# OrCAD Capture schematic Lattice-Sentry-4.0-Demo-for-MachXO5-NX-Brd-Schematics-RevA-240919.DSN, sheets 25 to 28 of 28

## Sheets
25 LEDS: size B
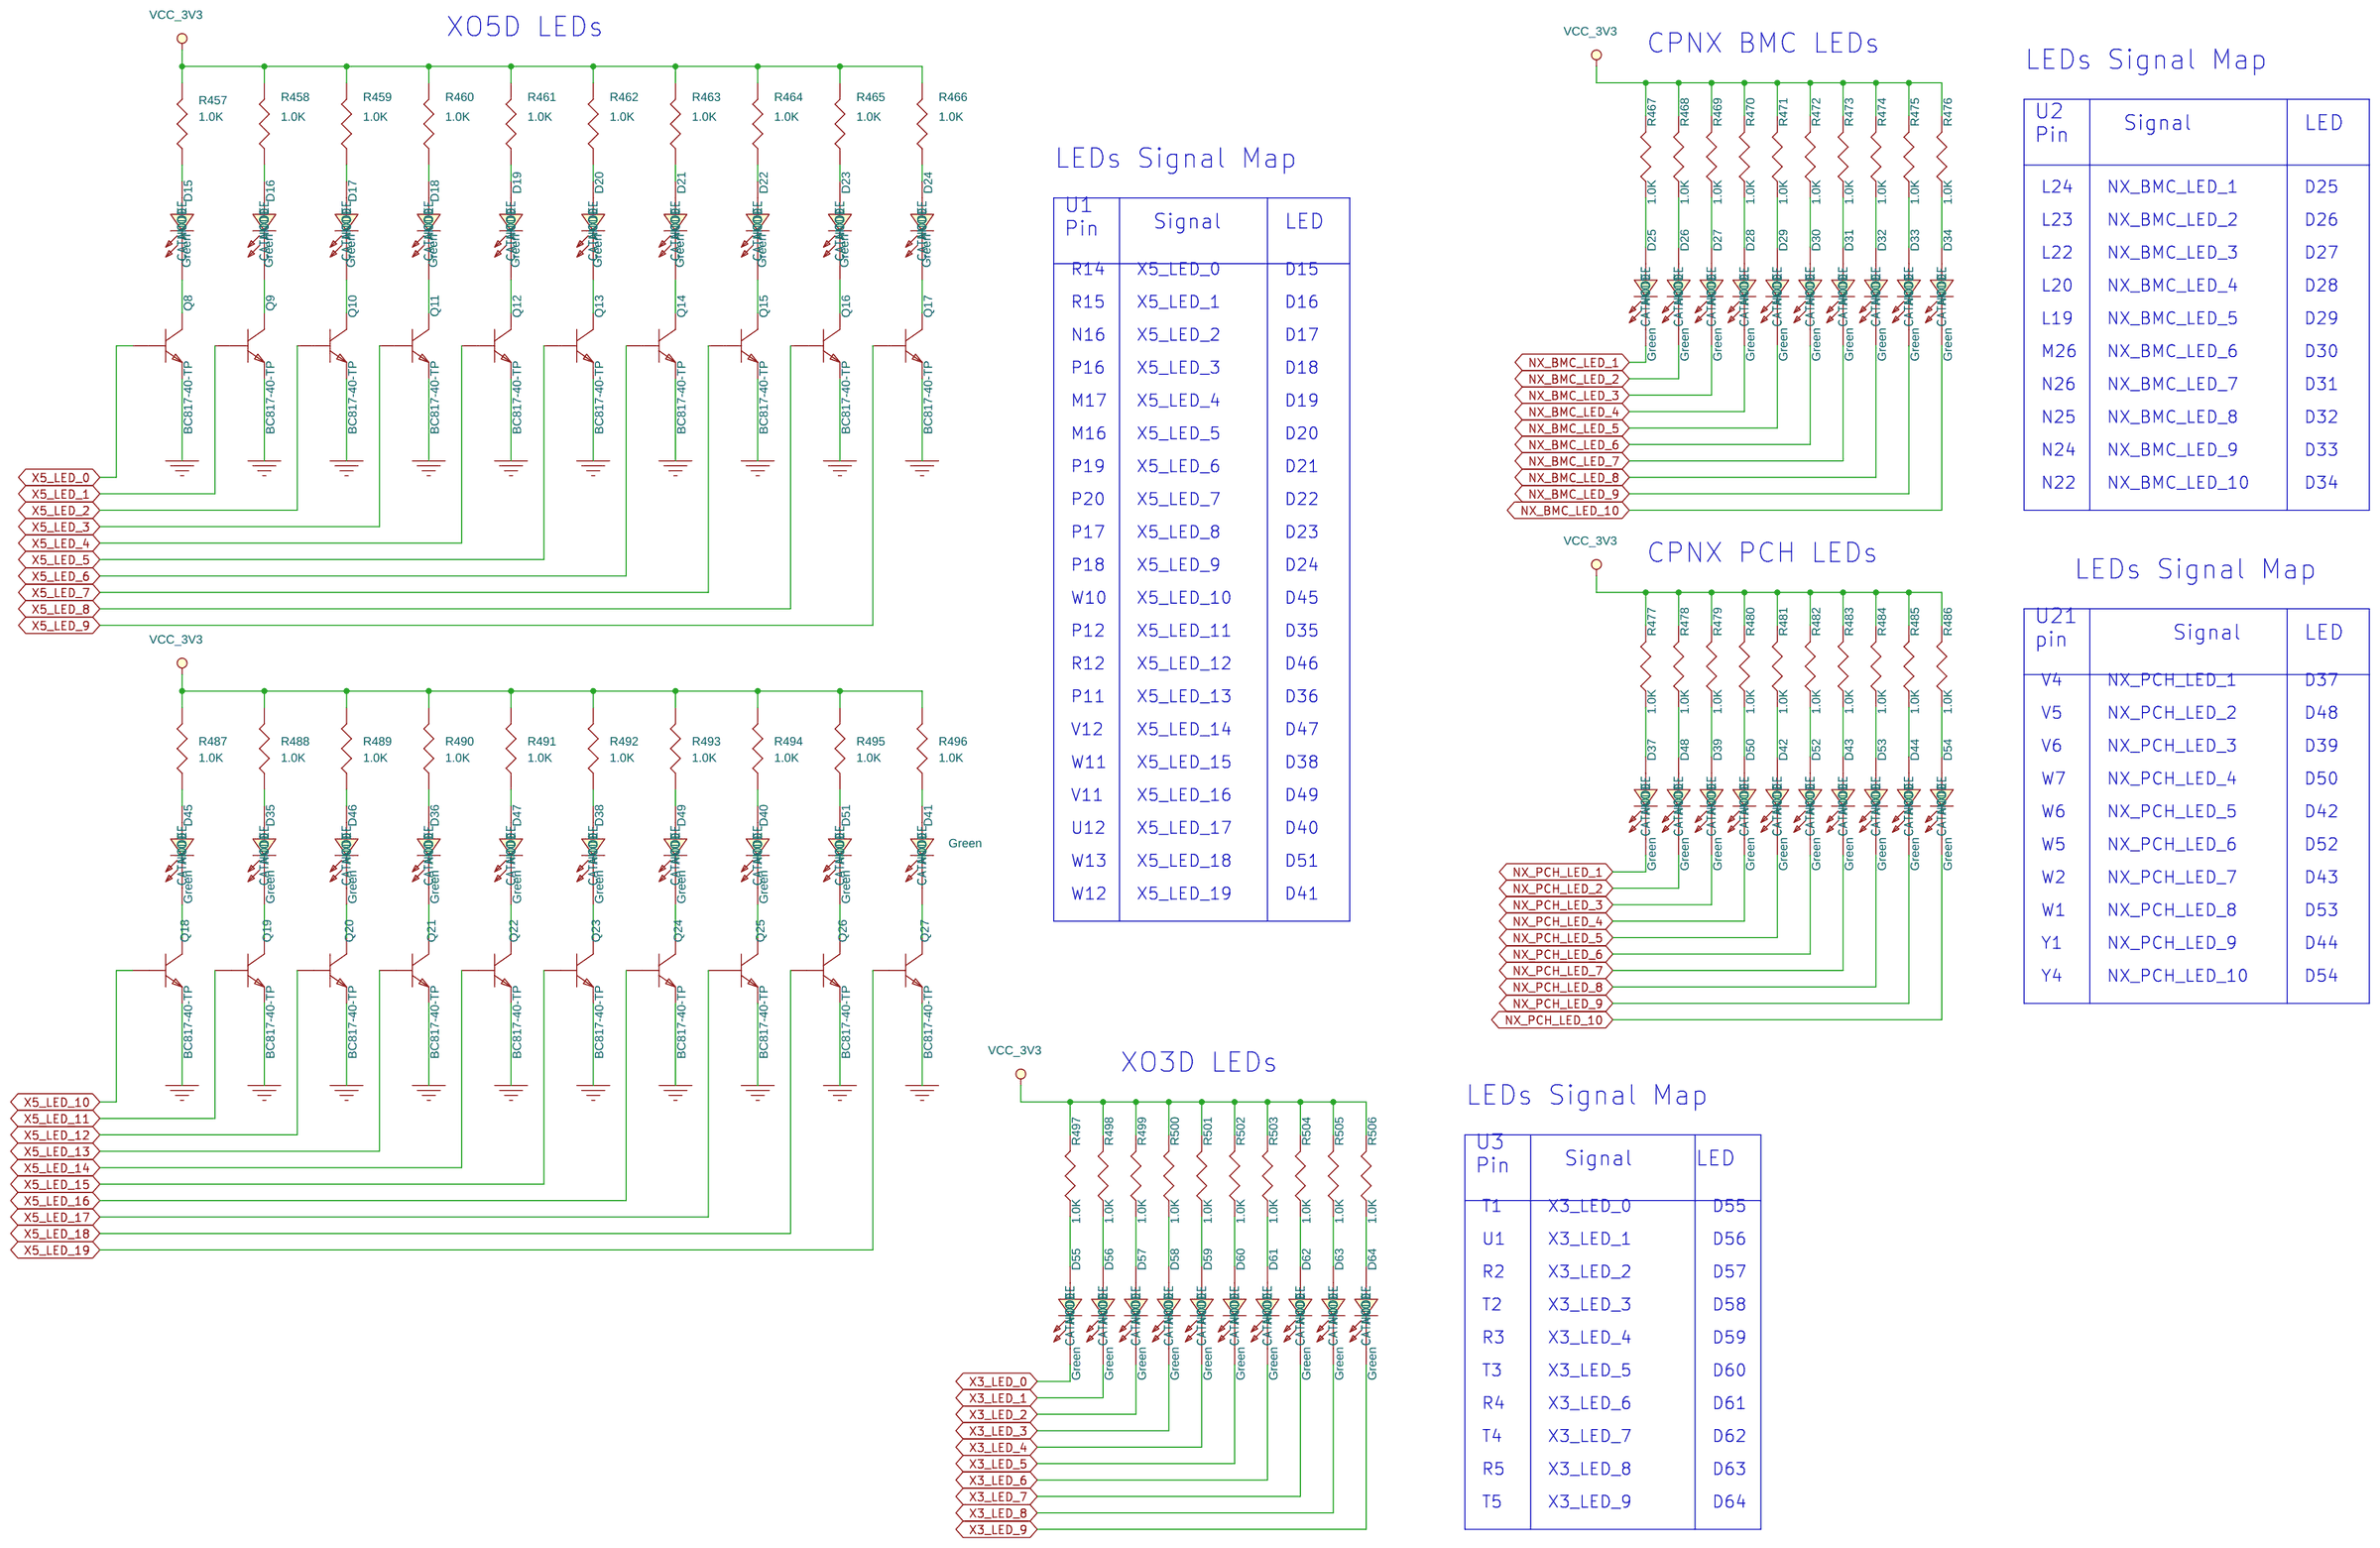
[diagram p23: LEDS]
26 DC-SCM CONNECTORS: size B
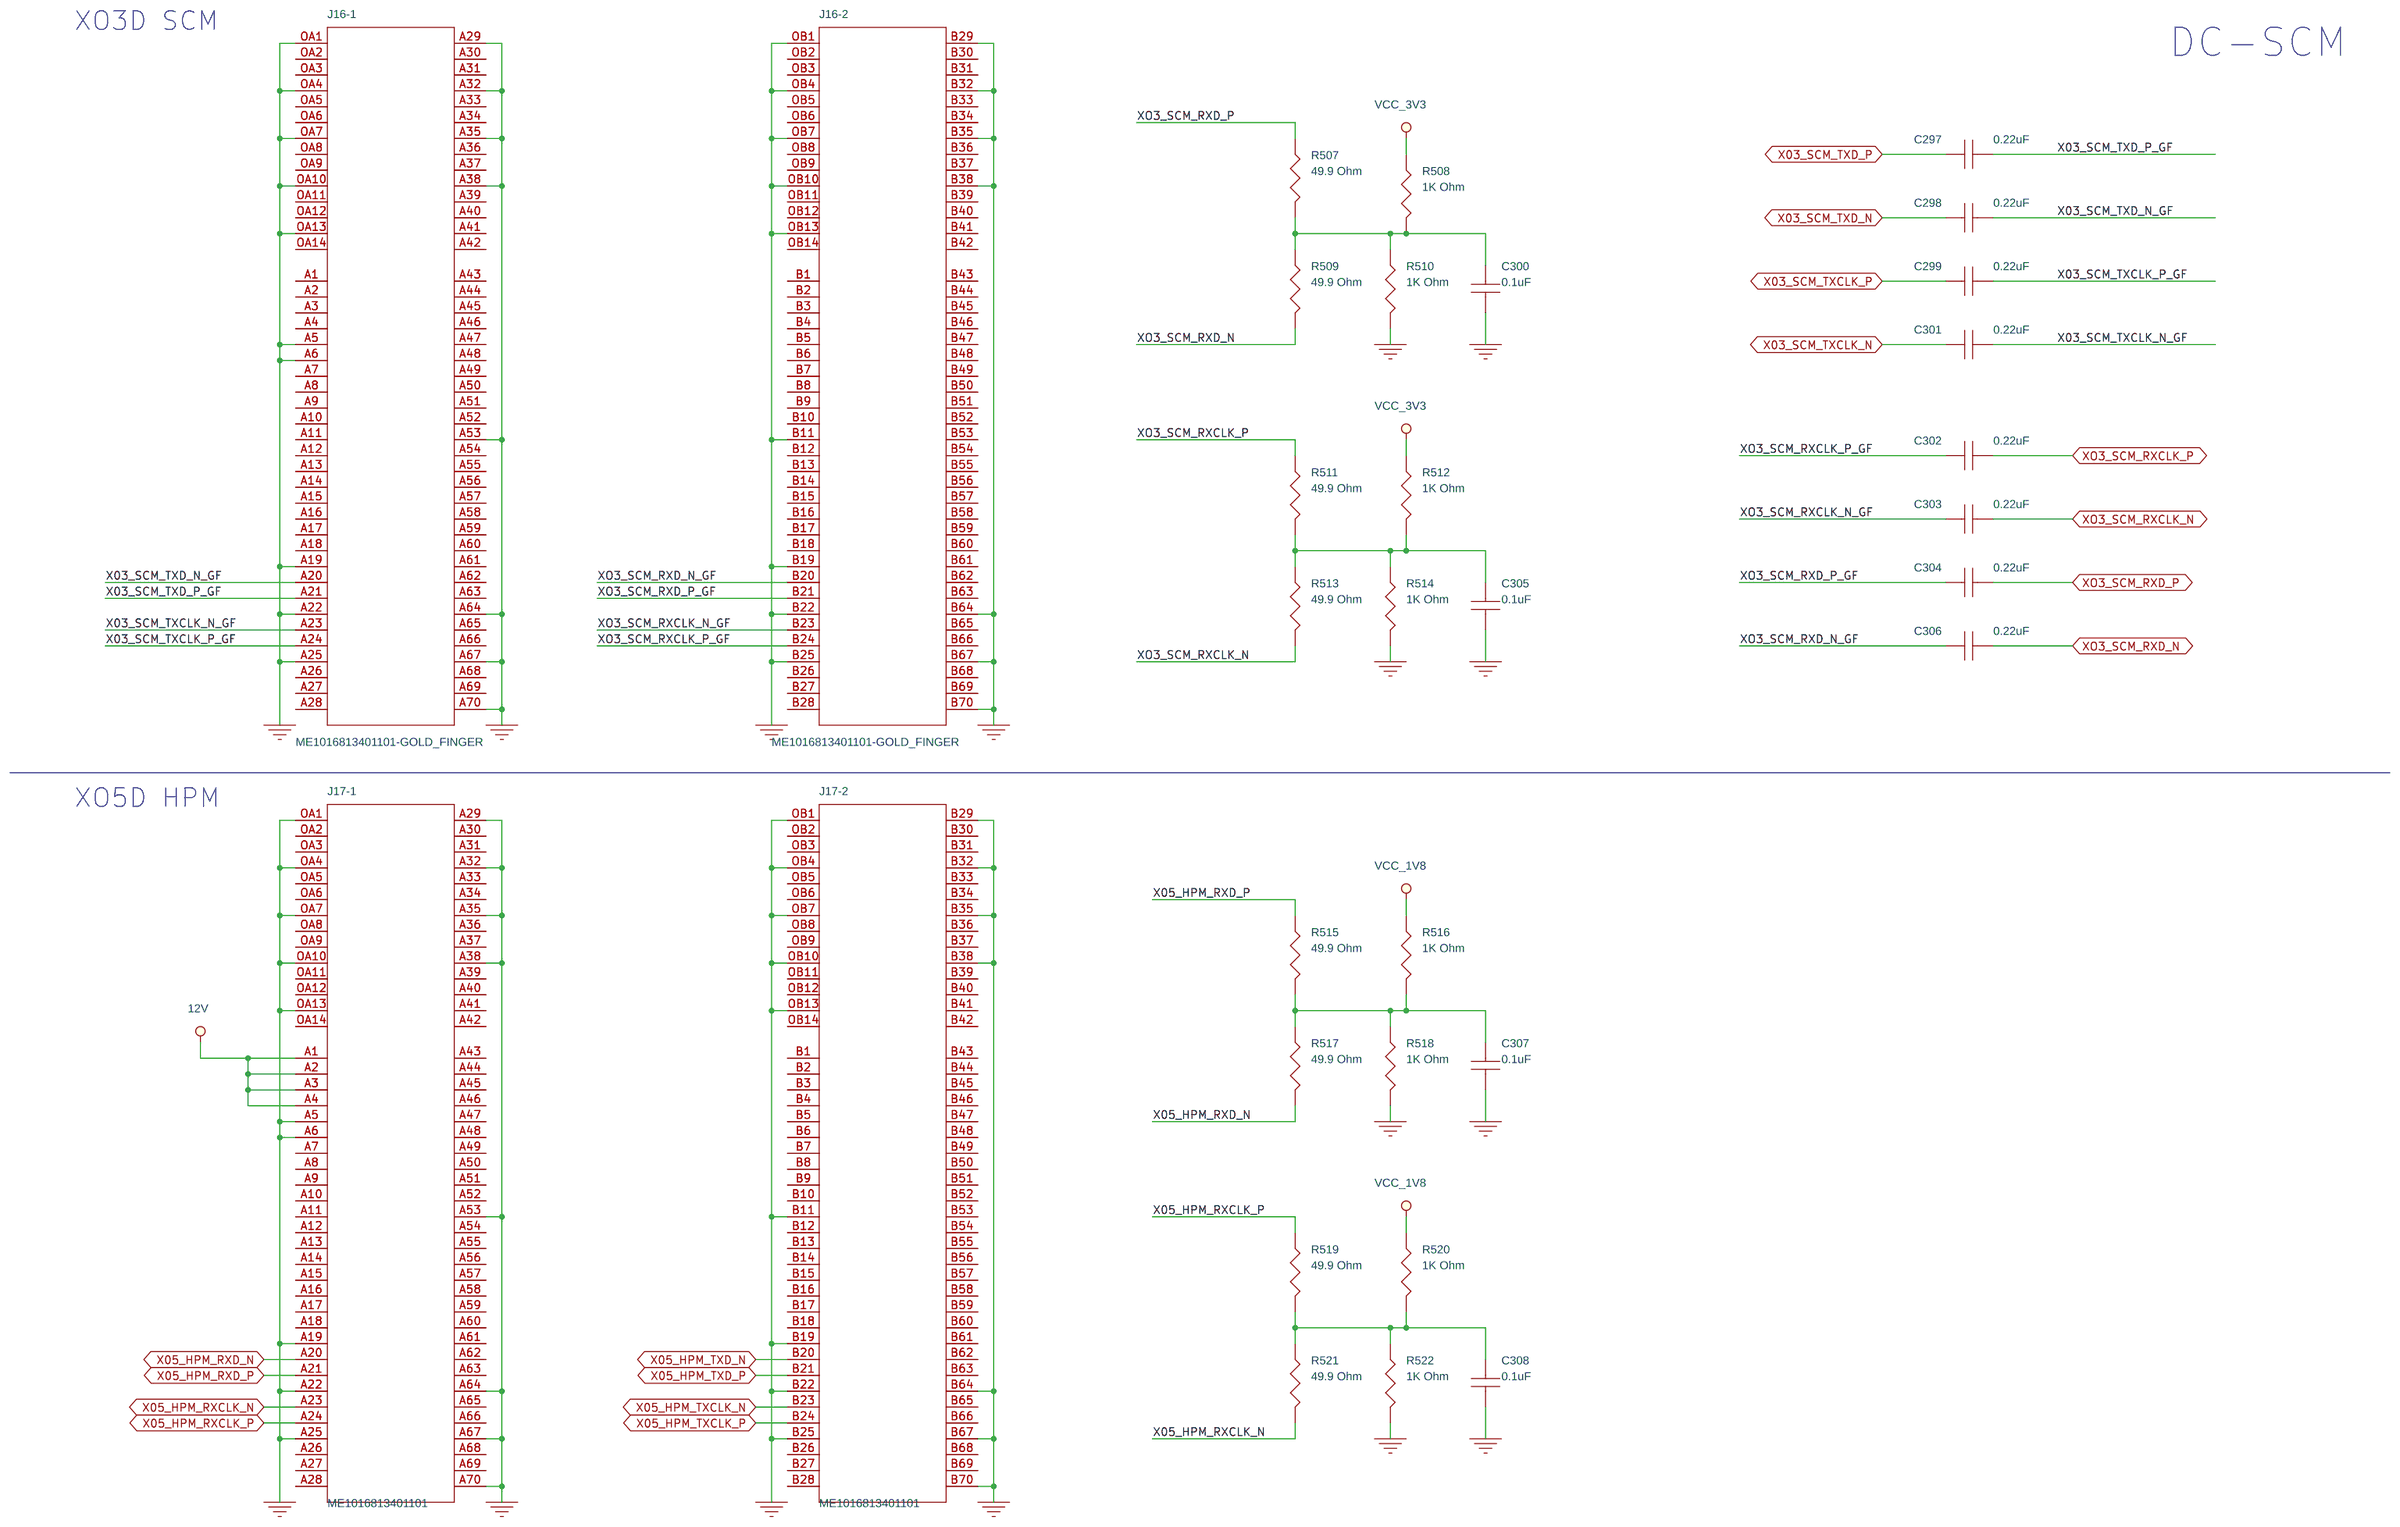
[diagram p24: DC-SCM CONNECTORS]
27 I3C PU: size B
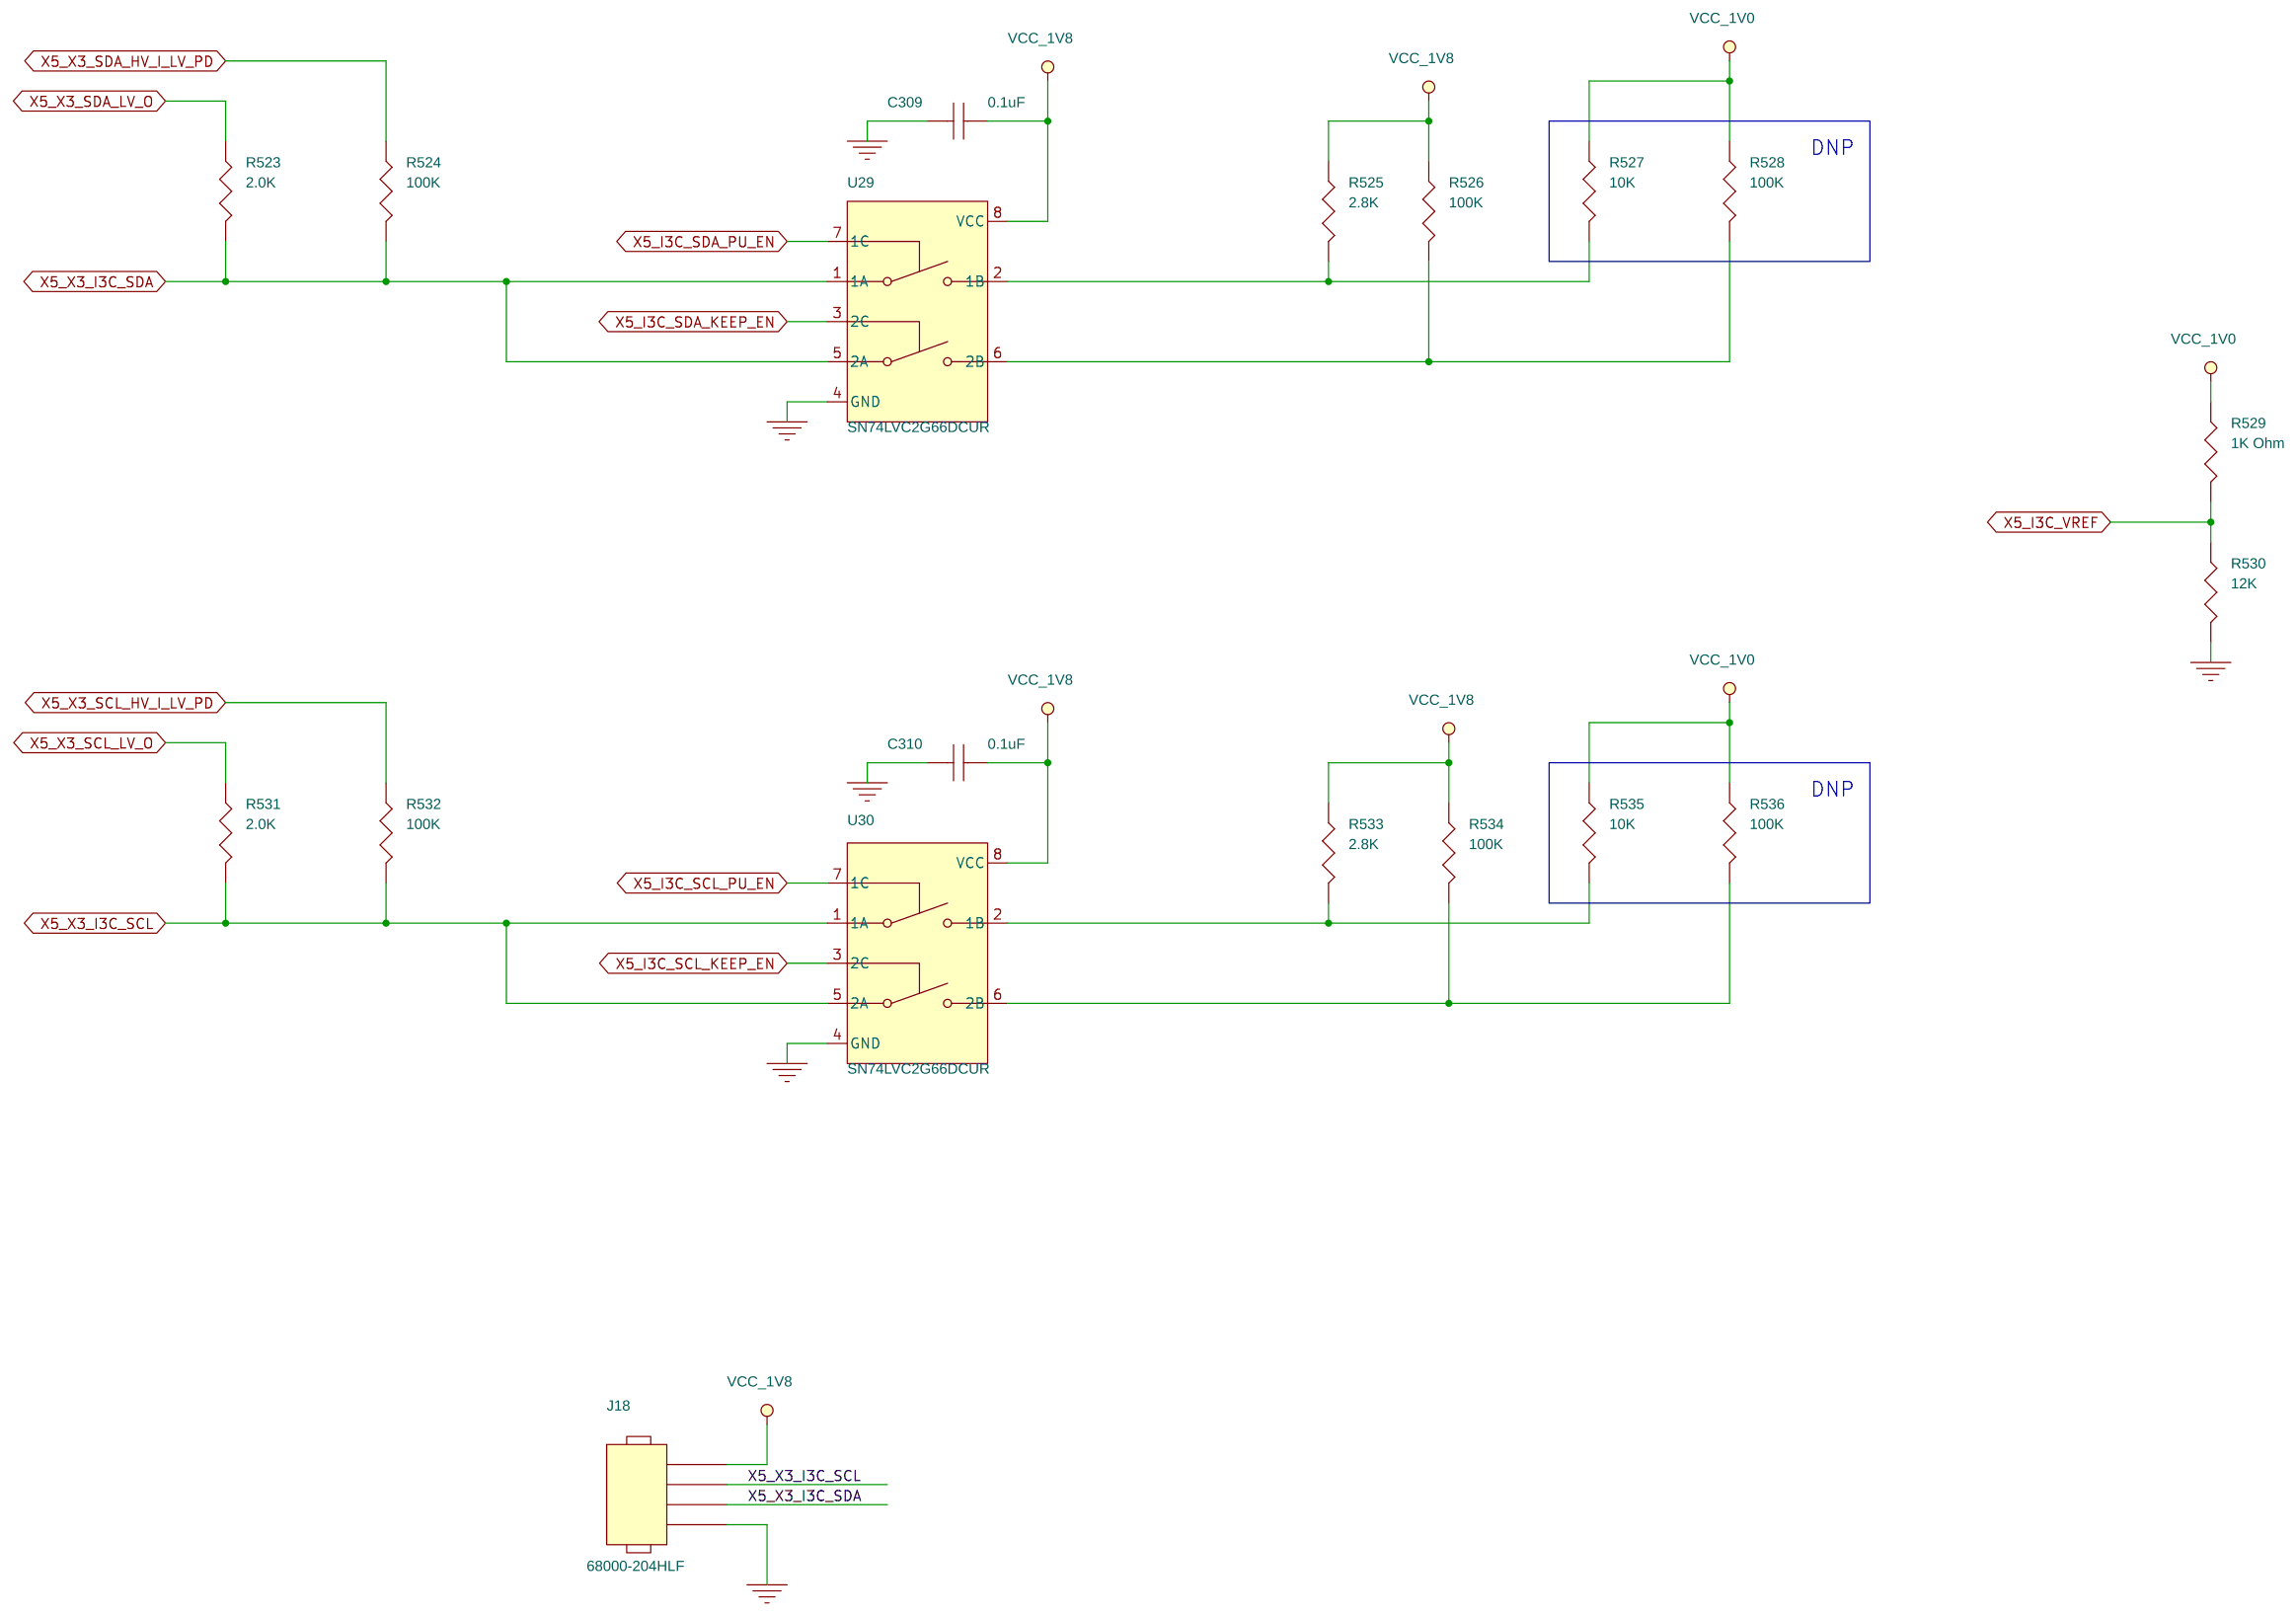
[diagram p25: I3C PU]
28 Power Regulators: size B
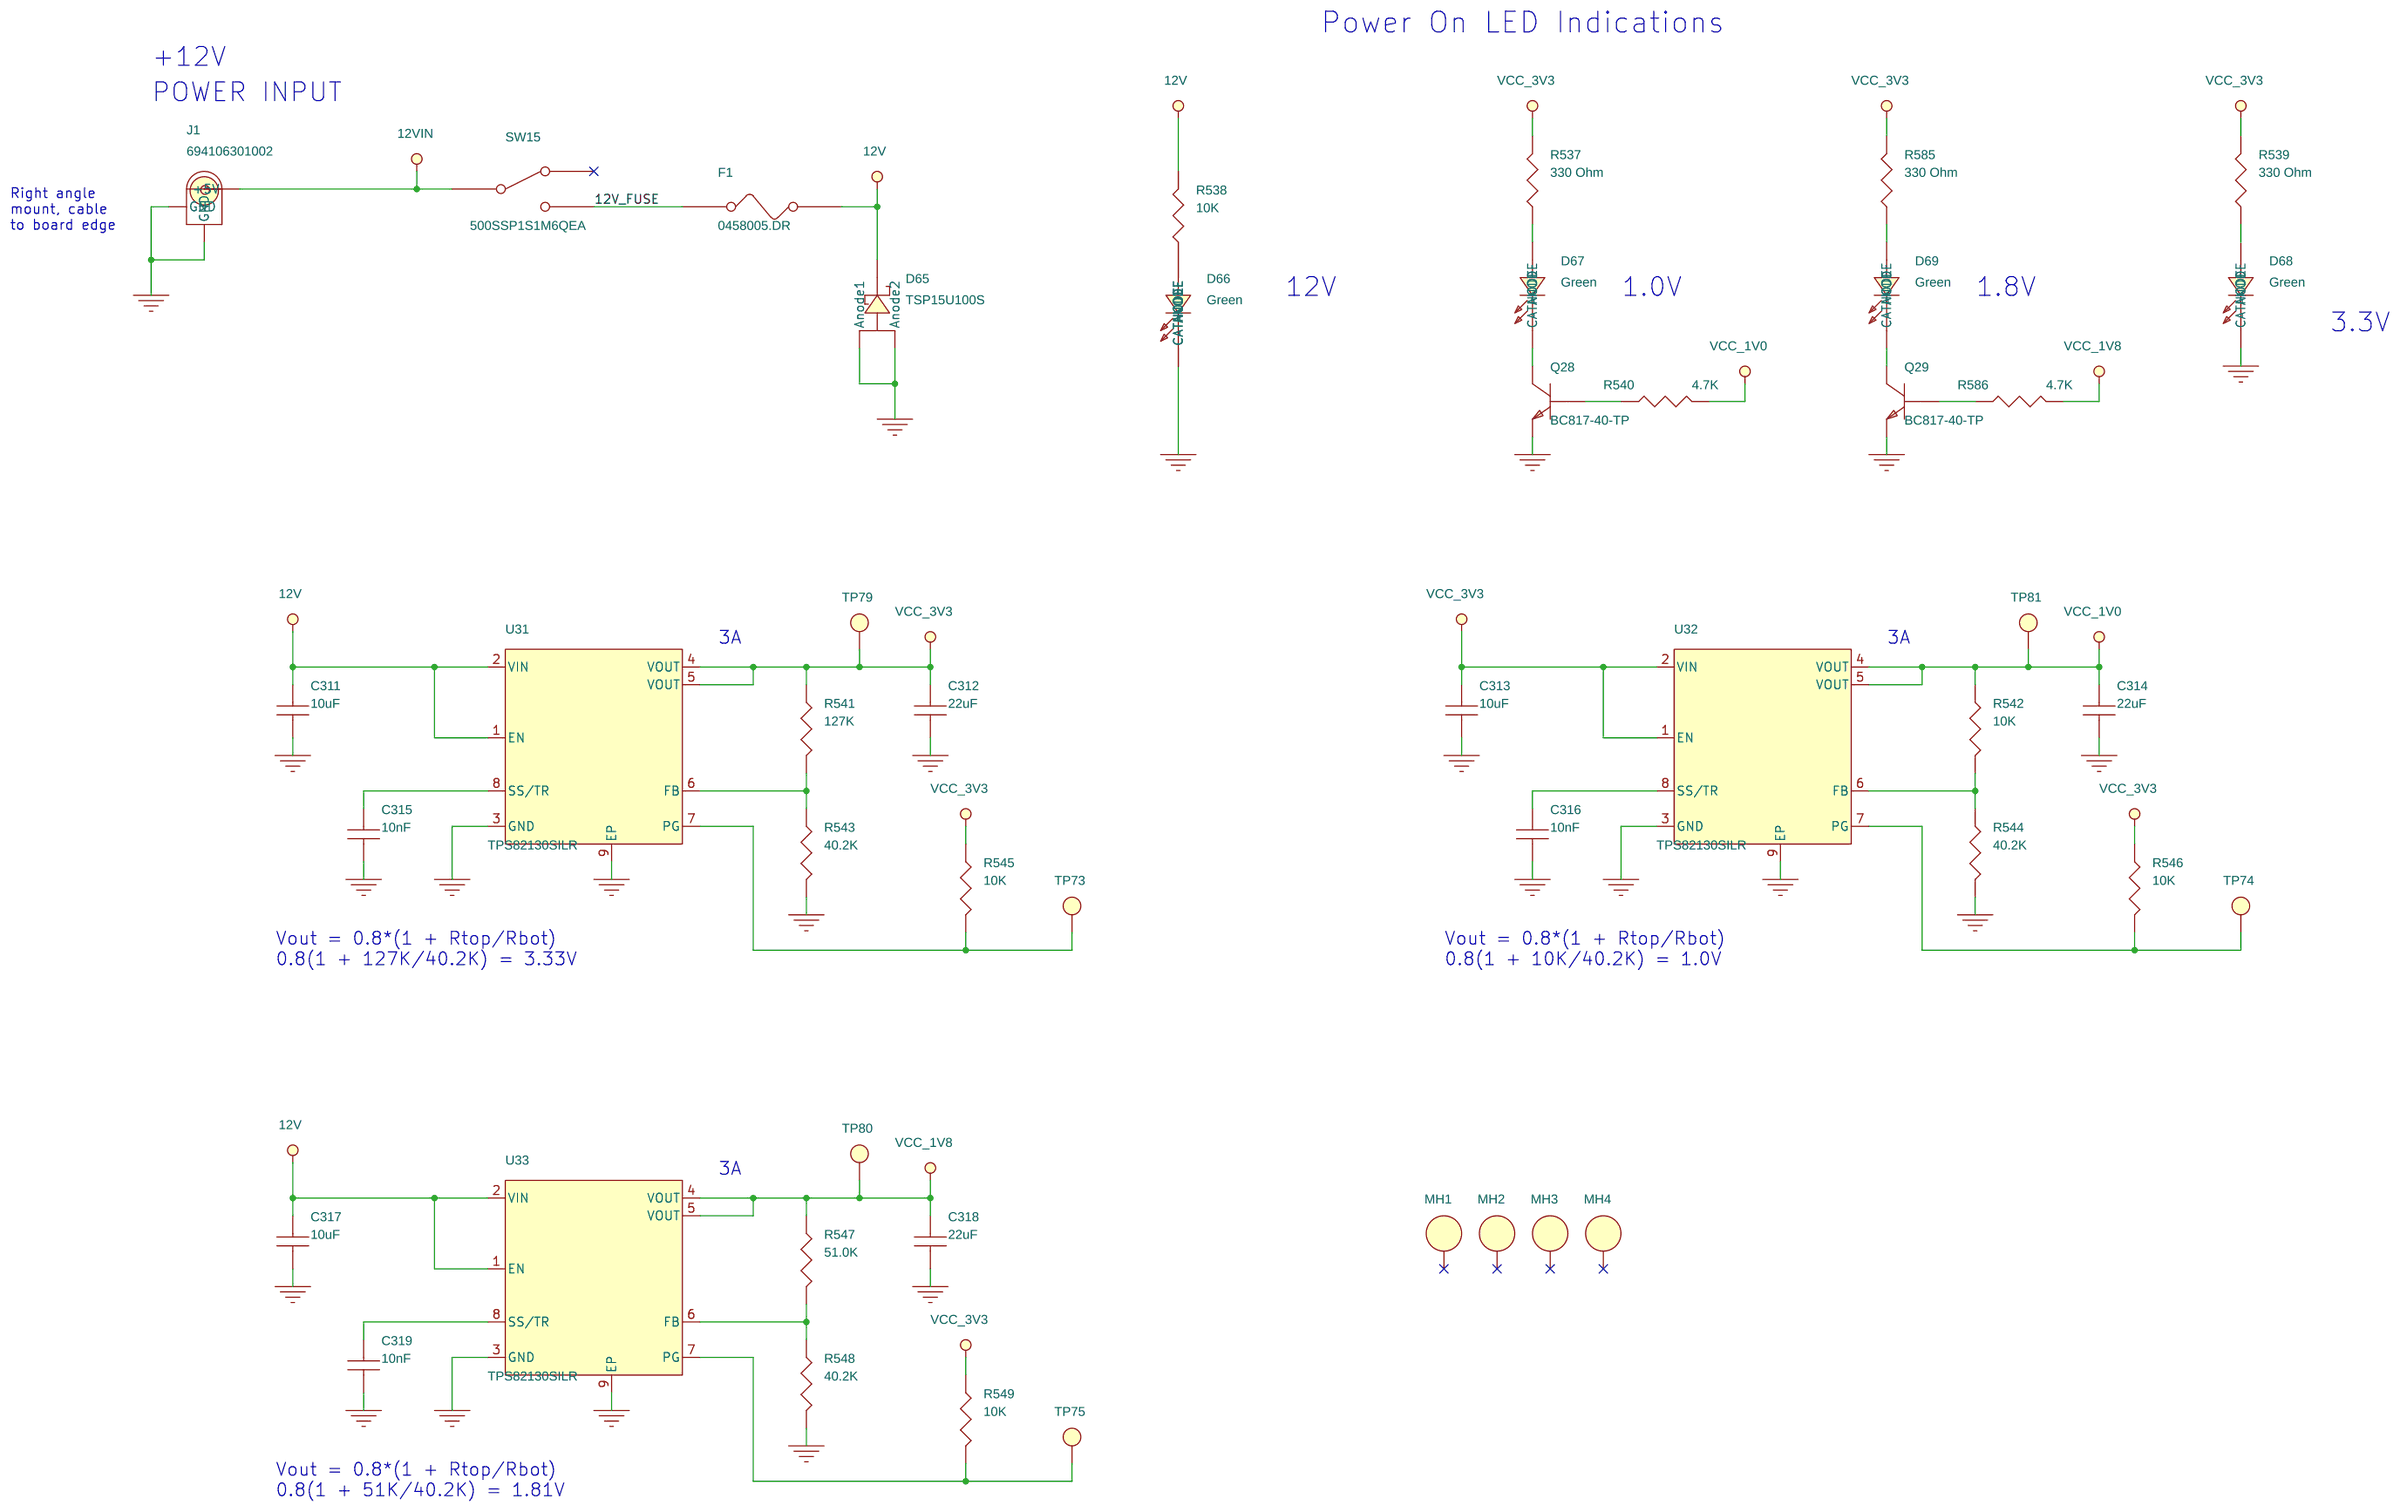
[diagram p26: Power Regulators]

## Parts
sheet DC-SCM CONNECTORS
C297  0.22uF  [C0402-L]
C298  0.22uF  [C0402-L]
C299  0.22uF  [C0402-L]
C300  0.1uF  [C0402-L]
C301  0.22uF  [C0402-L]
C302  0.22uF  [C0402-L]
C303  0.22uF  [C0402-L]
C304  0.22uF  [C0402-L]
C305  0.1uF  [C0402-L]
C306  0.22uF  [C0402-L]
C307  0.1uF  [C0402-L]
C308  0.1uF  [C0402-L]
J16  ME1016813401101-GOLD_FINGER  [AMPHENOL_ME1016813401101_GF]  (sections -1,-2)
J17  ME1016813401101  [AMPHENOL_ME1016813401101]  (sections -1,-2)
R507  49.9 Ohm  [R0402-L]
R508  1K Ohm  [R0402-L]
R509  49.9 Ohm  [R0402-L]
R510  1K Ohm  [R0402-L]
R511  49.9 Ohm  [R0402-L]
R512  1K Ohm  [R0402-L]
R513  49.9 Ohm  [R0402-L]
R514  1K Ohm  [R0402-L]
R515  49.9 Ohm  [R0402-L]
R516  1K Ohm  [R0402-L]
R517  49.9 Ohm  [R0402-L]
R518  1K Ohm  [R0402-L]
R519  49.9 Ohm  [R0402-L]
R520  1K Ohm  [R0402-L]
R521  49.9 Ohm  [R0402-L]
R522  1K Ohm  [R0402-L]
sheet I3C PU
C309  0.1uF  [C0402-L]
C310  0.1uF  [C0402-L]
J18  68000-204HLF  [CONN_61300411121_WRE]
R523  2.0K  [R0402-L]
R524  100K  [R0402-L]
R525  2.8K  [R0402-L]
R526  100K  [R0402-L]
R527  10K  [R0402-L]
R528  100K  [R0402-L]
R529  1K Ohm  [R0402-L]
R530  12K  [R0402-L]
R531  2.0K  [R0402-L]
R532  100K  [R0402-L]
R533  2.8K  [R0402-L]
R534  100K  [R0402-L]
R535  10K  [R0402-L]
R536  100K  [R0402-L]
U29  SN74LVC2G66DCUR  [DCU8]
U30  SN74LVC2G66DCUR  [DCU8]
sheet LEDS
D15  Green  [LED0603]
D16  Green  [LED0603]
D17  Green  [LED0603]
D18  Green  [LED0603]
D19  Green  [LED0603]
D20  Green  [LED0603]
D21  Green  [LED0603]
D22  Green  [LED0603]
D23  Green  [LED0603]
D24  Green  [LED0603]
D25  Green  [LED0603]
D26  Green  [LED0603]
D27  Green  [LED0603]
D28  Green  [LED0603]
D29  Green  [LED0603]
D30  Green  [LED0603]
D31  Green  [LED0603]
D32  Green  [LED0603]
D33  Green  [LED0603]
D34  Green  [LED0603]
D35  Green  [LED0603]
D36  Green  [LED0603]
D37  Green  [LED0603]
D38  Green  [LED0603]
D39  Green  [LED0603]
D40  Green  [LED0603]
D41  Green  [LED0603]
D42  Green  [LED0603]
D43  Green  [LED0603]
D44  Green  [LED0603]
D45  Green  [LED0603]
D46  Green  [LED0603]
D47  Green  [LED0603]
D48  Green  [LED0603]
D49  Green  [LED0603]
D50  Green  [LED0603]
D51  Green  [LED0603]
D52  Green  [LED0603]
D53  Green  [LED0603]
D54  Green  [LED0603]
D55  Green  [LED0603]
D56  Green  [LED0603]
D57  Green  [LED0603]
D58  Green  [LED0603]
D59  Green  [LED0603]
D60  Green  [LED0603]
D61  Green  [LED0603]
D62  Green  [LED0603]
D63  Green  [LED0603]
D64  Green  [LED0603]
Q8  BC817-40-TP  [SOT-23-3]
Q9  BC817-40-TP  [SOT-23-3]
Q10  BC817-40-TP  [SOT-23-3]
Q11  BC817-40-TP  [SOT-23-3]
Q12  BC817-40-TP  [SOT-23-3]
Q13  BC817-40-TP  [SOT-23-3]
Q14  BC817-40-TP  [SOT-23-3]
Q15  BC817-40-TP  [SOT-23-3]
Q16  BC817-40-TP  [SOT-23-3]
Q17  BC817-40-TP  [SOT-23-3]
Q18  BC817-40-TP  [SOT-23-3]
Q19  BC817-40-TP  [SOT-23-3]
Q20  BC817-40-TP  [SOT-23-3]
Q21  BC817-40-TP  [SOT-23-3]
Q22  BC817-40-TP  [SOT-23-3]
Q23  BC817-40-TP  [SOT-23-3]
Q24  BC817-40-TP  [SOT-23-3]
Q25  BC817-40-TP  [SOT-23-3]
Q26  BC817-40-TP  [SOT-23-3]
Q27  BC817-40-TP  [SOT-23-3]
R457  1.0K  [R0603-L]
R458  1.0K  [R0603-L]
R459  1.0K  [R0603-L]
R460  1.0K  [R0603-L]
R461  1.0K  [R0603-L]
R462  1.0K  [R0603-L]
R463  1.0K  [R0603-L]
R464  1.0K  [R0603-L]
R465  1.0K  [R0603-L]
R466  1.0K  [R0603-L]
R467  1.0K  [R0603-L]
R468  1.0K  [R0603-L]
R469  1.0K  [R0603-L]
R470  1.0K  [R0603-L]
R471  1.0K  [R0603-L]
R472  1.0K  [R0603-L]
R473  1.0K  [R0603-L]
R474  1.0K  [R0603-L]
R475  1.0K  [R0603-L]
R476  1.0K  [R0603-L]
R477  1.0K  [R0603-L]
R478  1.0K  [R0603-L]
R479  1.0K  [R0603-L]
R480  1.0K  [R0603-L]
R481  1.0K  [R0603-L]
R482  1.0K  [R0603-L]
R483  1.0K  [R0603-L]
R484  1.0K  [R0603-L]
R485  1.0K  [R0603-L]
R486  1.0K  [R0603-L]
R487  1.0K  [R0603-L]
R488  1.0K  [R0603-L]
R489  1.0K  [R0603-L]
R490  1.0K  [R0603-L]
R491  1.0K  [R0603-L]
R492  1.0K  [R0603-L]
R493  1.0K  [R0603-L]
R494  1.0K  [R0603-L]
R495  1.0K  [R0603-L]
R496  1.0K  [R0603-L]
R497  1.0K  [R0603-L]
R498  1.0K  [R0603-L]
R499  1.0K  [R0603-L]
R500  1.0K  [R0603-L]
R501  1.0K  [R0603-L]
R502  1.0K  [R0603-L]
R503  1.0K  [R0603-L]
R504  1.0K  [R0603-L]
R505  1.0K  [R0603-L]
R506  1.0K  [R0603-L]
sheet Power Regulators
C311  10uF  [C0805-L]
C312  22uF  [C0805-L]
C313  10uF  [C0805-L]
C314  22uF  [C0805-L]
C315  10nF  [C0402-L]
C316  10nF  [C0402-L]
C317  10uF  [C0805-L]
C318  22uF  [C0805-L]
C319  10nF  [C0402-L]
D65  TSP15U100S  [TO-227A_TS]
D66  Green  [LED0603]
D67  Green  [LED0603]
D68  Green  [LED0603]
D69  Green  [LED0603]
F1  0458005.DR  [0458Series_LTF-L]
J1  694106301002  [CONN3_01002_WRE]
MH1  MH  [MTG125]
MH2  MH  [MTG125]
MH3  MH  [MTG125]
MH4  MH  [MTG125]
Q28  BC817-40-TP  [SOT-23-3]
Q29  BC817-40-TP  [SOT-23-3]
R537  330 Ohm  [R0402-L]
R538  10K  [R0402-L]
R539  330 Ohm  [R0402-L]
R540  4.7K  [R0402-L]
R541  127K  [R0402-L]
R542  10K  [R0402-L]
R543  40.2K  [R0402-L]
R544  40.2K  [R0402-L]
R545  10K  [R0402-L]
R546  10K  [R0402-L]
R547  51.0K  [R0402-L]
R548  40.2K  [R0402-L]
R549  10K  [R0402-L]
R585  330 Ohm  [R0402-L]
R586  4.7K  [R0402-L]
SW15  500SSP1S1M6QEA  [SW_500SSP1S1M6QEA]
TP73  TP1  [TPd39c60]
TP74  TP1  [TPd39c60]
TP75  TP1  [TPd39c60]
TP79  TP1  [TPd39c60]
TP80  TP1  [TPd39c60]
TP81  TP1  [TPd39c60]
U31  TPS82130SILR  [CONV_TPS82140SILR]
U32  TPS82130SILR  [CONV_TPS82140SILR]
U33  TPS82130SILR  [CONV_TPS82140SILR]

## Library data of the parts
C297-C299 C301-C304 C306 = CAP_NP: 0.22 µF ±10% 50V Ceramic Capacitor X5R 0402 (1005 Metric); Manufacturer: Murata; Manufacturer Part Number: GRM155R61H224KE01W; Part Number: GRM155R61H224KE01W; Part type: Ceramic; Tolerance: 10%; Voltage: 50V; Datasheet: https://search.murata.co.jp/Ceramy/image/img/A01X/G101/ENG/GRM155R61H224KE01-01A.pdf
C300 C305 C307-C310 = CAP_NP: 0.1 µF ±10% 50V Ceramic Capacitor X7R 0402 (1005 Metric); Manufacturer: Murata; Manufacturer Part Number: GRM155R71H104KE14J; Part Number: GRM155R71H104KE14J; Part type: Ceramic; Tolerance: 10%; Voltage: 50V; Datasheet: https://search.murata.co.jp/Ceramy/image/img/A01X/G101/ENG/GRM155R71H104KE14-01.pdf
J16 = ME1016813401101: 168 Position Gold Finger  - Dual Edge Gold 0.024" (0.60mm); Assy: DNL; Manufacturer: NA; Part Type: Connector
J17 = ME1016813401101: 168 Position Female Connector Non Specified - Dual Edge Gold 0.024" (0.60mm) Black; Manufacturer: Amphenol; Part Type: Connector; Datasheet: https://cdn.amphenol-cs.com/media/wysiwyg/files/drawing/cme10168x340x10x.pdf
R507 R509 R511 R513 R515 R517 R519 R521 = R: 49.9 Ohms ±1% 0.063W, 1/16W Chip Resistor 0402 (1005 Metric) Moisture Resistant Thick Film; Manufacturer: Yageo; Manufacturer Part Number: RC0402FR-0749R9L; Part Number: RC0402FR-0749R9L; Part type: Thick Film; Power: 1/16W; Tolerance: 1%; Datasheet: https://www.yageo.com/upload/media/product/app/datasheet/rchip/pyu-rc_group_51_rohs_l.pdf
R508 R510 R512 R514 R516 R518 R520 R522 R529 = R: 1 kOhms ±1% 0.063W, 1/16W Chip Resistor 0402 (1005 Metric) Thick Film; Manufacturer: Yageo; Manufacturer Part Number: RC0402FR-71K2P / RC0402FR-0733R2P; Part Number: RC0402FR-071KP / RC0402FR-0733R2P / RC0402FR-0733R2P; Part type: Thick Film; Power: 1/16W; Tolerance: 1%; Datasheet: https://www.yageo.com/upload/media/product/products/datasheet/rchip/PYu-RC_51_RoHS_P_4.pdf
J18 = HEADER_4: Connector Header Through Hole 4 position 0.100" (2.54mm); Manufacturer: Amphenol; Part Type: Connector; Datasheet: https://cdn.amphenol-cs.com/media/wysiwyg/files/drawing/68000.pdf
R523 R531 = R: 2 kOhms ±1% 0.063W, 1/16W Chip Resistor 0402 (1005 Metric) Moisture Resistant Thick Film; Manufacturer: Yageo; Manufacturer Part Number: RC0402FR-072KL; Part Number: RC0402FR-072KL; Part type: Thick Film; Power: 1.16W; Tolerance: 1%; Datasheet: https://www.yageo.com/upload/media/product/app/datasheet/rchip/pyu-rc_group_51_rohs_l.pdf
R524 R526 R532 R534 = R: 100 kOhms ±1% 0.063W, 1/16W Chip Resistor 0402 (1005 Metric) Moisture Resistant Thick Film; Manufacturer: Yageo; Manufacturer Part Number: RC0402FR-07100KL; Part Number: RC0402FR-07100KL; Part type: Thick Film; Power: 1/16W; Tolerance: 1%; Datasheet: https://www.yageo.com/upload/media/product/app/datasheet/rchip/pyu-rc_group_51_rohs_l.pdf
R525 R533 = R: 2.8 kOhms ±1% 0.063W, 1/16W Chip Resistor 0402 (1005 Metric) Moisture Resistant Thick Film; Manufacturer: Yageo; Manufacturer Part Number: RC0402FR-072K8L; Part Number: RC0402FR-072K8L; Part type: Thick Film; Power: 1/16W; Tolerance: 1%; Datasheet: https://www.yageo.com/upload/media/product/app/datasheet/rchip/pyu-rc_group_51_rohs_l.pdf
R527 R535 = R: 10 kOhms ±1% 0.063W, 1/16W Chip Resistor 0402 (1005 Metric) Thick Film; Assy: DNL; Manufacturer: Yageo; Manufacturer Part Number: RC0402FR-0710KP; Part Number: RC0402FR-0710KP; Part type: Thick Film; Power: 1/16W; Tolerance: 1%; Datasheet: https://www.yageo.com/upload/media/product/products/datasheet/rchip/PYu-RC_51_RoHS_P_4.pdf
R528 R536 = R: 100 kOhms ±1% 0.063W, 1/16W Chip Resistor 0402 (1005 Metric) Moisture Resistant Thick Film; Assy: DNL; Manufacturer: Yageo; Manufacturer Part Number: RC0402FR-07100KL; Part Number: RC0402FR-07100KL; Part type: Thick Film; Power: 1/16W; Tolerance: 1%; Datasheet: https://www.yageo.com/upload/media/product/app/datasheet/rchip/pyu-rc_group_51_rohs_l.pdf
R530 = R: 12 kOhms ±1% 0.063W, 1/16W Chip Resistor 0402 (1005 Metric) Moisture Resistant Thick Film; Manufacturer: Yageo; Manufacturer Part Number: RC0402FR-0712KL; Part Number: RC0402FR-0712KL; Part type: Thick Film; Power: 1/16W; Tolerance: 1%; Datasheet: https://www.yageo.com/upload/media/product/productsearch/datasheet/rchip/PYu-RC_Group_51_RoHS_L_12.pdf
U29 U30 = SN74LVC2G66: IC SWITCH SPST-NOX2 10OHM 8VSSOP; Manufacturer: Texas Instruments; Part Type: Analog Switch; Datasheet: https://www.ti.com/general/docs/suppproductinfo.tsp?distId=10&gotoUrl=https%3A%2F%2Fwww.ti.com%2Flit%2Fgpn%2Fsn74lvc2g66
D15-D64 D66-D69 = LED_0: Green 572nm LED indication - Discrete  2.2V 0603; Manufacturer: Rohm Semiconductor; Manufacturer Part Number: SML-D12M8WT86; Part Number: SML-D12M8WT86; Part type: LED; Voltage: 2.2V; Datasheet: https://fscdn.rohm.com/en/products/databook/datasheet/opto/led/chip_mono/sml-d12x8_d13x8-e.pdf
Q8-Q29 = NPN_BEC_0: Bipolar (BJT) Transistor NPN 45 V 800 mA 100MHz 310 mW Surface Mount SOT-23; Manufacturer: Micro Commercial; Part Type: BJT_NPN; Datasheet: https://www.mccsemi.com/pdf/Products/BC817-16~BC817-40(SOT-23).pdf
R457-R506 = R: 1 kOhms ±1% 0.1W, 1/10W Chip Resistor 0603 (1608 Metric) Moisture Resistant Thick Film; Manufacturer: Yageo; Manufacturer Part Number: RC0603FR-071KL; Part Number: RC0603FR-071KL; Part type: Thick Film; Power: 1/10W; Tolerance: 1%; Datasheet: https://www.yageo.com/upload/media/product/app/datasheet/rchip/pyu-rc_group_51_rohs_l.pdf
C311 C313 C317 = CAP_NP: 10 µF ±10% 25V Ceramic Capacitor X5R 0805 (2012 Metric); Manufacturer: Murata; Manufacturer Part Number: GRM21BR61E106KA73K; Part Number: GRM21BR61E106KA73K; Part type: Ceramic; Tolerance: 10%; Voltage: 25V; Datasheet: https://search.murata.co.jp/Ceramy/image/img/A01X/G101/ENG/GRM21BR61E106KA73-01.pdf
C312 C314 C318 = CAP_NP: 22 µF ±20% 25V Ceramic Capacitor X5R 0805 (2012 Metric); Manufacturer: Murata; Manufacturer Part Number: GRM21BR61E226ME44K; Part Number: GRM21BR61E226ME44K; Part type: Ceramic; Tolerance: 20%; Voltage: 25V; Datasheet: https://search.murata.co.jp/Ceramy/image/img/A01X/G101/ENG/GRM21BR61E226ME44-01.pdf
C315 C316 C319 = CAP_NP: 10000 pF ±10% 50V Ceramic Capacitor X7R 0402 (1005 Metric); Manufacturer: Murata; Manufacturer Part Number: GRM155R71H103KA88D; Part Number: GRM155R71H103KA88D; Part type: Ceramic; Tolerance: 10%; Voltage: 50V; Datasheet: https://search.murata.co.jp/Ceramy/image/img/A01X/G101/ENG/GRM155R71H103KA88-01.pdf
D65 = SCHOTTKY_0: Diode Schottky 100 V 15A Surface Mount TO-277A (SMPC); Current: 15A; Manufacturer: Taiwan Semiconductor; Part type: SCHOTTKY; Voltage: 100V; Datasheet: https://www.taiwansemi.com/assets/uploads/datasheet/TSP15U100S_E2103.pdf
F1 = FUSE_SM: 5 A 32 V AC 75 V DC Fuse Board Mount (Cartridge Style Excluded) Surface Mount 1206 (3216 Metric); Current: 5A; Manufacturer: Little Fuse; Part type: Fuse; Voltage: 75VDC; Datasheet: https://www.littelfuse.com/~/media/electronics/datasheets/fuses/littelfuse_fuse_458_datasheet.pdf.pdf
J1 = J_JACK_2.10mm: Power Barrel Connector Jack 2.10mm ID (0.083"), 5.50mm OD (0.217") Through Hole, Right Angle; Manufacturer: Wurth; Part Type: Connector; Datasheet: https://www.we-online.com/katalog/datasheet/6941xx301002.pdf
MH1-MH4 = MH: Mounting Hole; Manufacturer: NA; Manufacturer Part Number: NA; Datasheet: NA
R537 R539 R585 = R: 330 Ohms ±1% 0.063W, 1/16W Chip Resistor 0402 (1005 Metric) Moisture Resistant Thick Film; Manufacturer: Yageo; Manufacturer Part Number: RC0402FR-07330RL; Part Number: RC0402FR-07330RL; Part type: Thick Film; Power: 1/16W; Tolerance: 1%; Datasheet: https://www.yageo.com/upload/media/product/productsearch/datasheet/rchip/PYu-RC_Group_51_RoHS_L_12.pdf
R538 R542 R545 R546 R549 = R: 10 kOhms ±1% 0.063W, 1/16W Chip Resistor 0402 (1005 Metric) Thick Film; Manufacturer: Yageo; Manufacturer Part Number: RC0402FR-0710KP; Part Number: RC0402FR-0710KP; Part type: Thick Film; Power: 1/16W; Tolerance: 1%; Datasheet: https://www.yageo.com/upload/media/product/products/datasheet/rchip/PYu-RC_51_RoHS_P_4.pdf
R540 R586 = R: 4.7 kOhms ±1% 0.063W, 1/16W Chip Resistor 0402 (1005 Metric) Thick Film; Manufacturer: Yageo; Manufacturer Part Number: RC0402FR-074K7P; Part Number: RC0402FR-074K7P; Part type: Thick Film; Power: 1/16W; Tolerance: 1%; Datasheet: https://www.yageo.com/upload/media/product/products/datasheet/rchip/PYu-RC_51_RoHS_P_4.pdf
R541 = R: 127 kOhms ±1% 0.063W, 1/16W Chip Resistor 0402 (1005 Metric) Moisture Resistant Thick Film; Manufacturer: Yageo; Manufacturer Part Number: RC0402FR-07127KL; Part Number: RC0402FR-07127KL; Part type: Thick Film; Power: 1/16W; Tolerance: 1%; Datasheet: https://www.yageo.com/upload/media/product/app/datasheet/rchip/pyu-rc_group_51_rohs_l.pdf
R543 R544 R548 = R: 40.2 kOhms ±1% 0.063W, 1/16W Chip Resistor 0402 (1005 Metric) Moisture Resistant Thick Film; Manufacturer: Yageo; Manufacturer Part Number: RC0402FR-0740K2L; Part Number: RC0402FR-0740K2L; Part type: Thick Film; Power: 1/16W; Tolerance: 1%; Datasheet: https://www.yageo.com/upload/media/product/app/datasheet/rchip/pyu-rc_group_51_rohs_l.pdf
R547 = R: 51 kOhms ±1% 0.063W, 1/16W Chip Resistor 0402 (1005 Metric) Moisture Resistant Thick Film; Manufacturer: Yageo; Manufacturer Part Number: RC0402FR-0751KL; Part Number: RC0402FR-0751KL; Part type: Thick Film; Power: 1/16W; Tolerance: 1%; Datasheet: https://www.yageo.com/upload/media/product/app/datasheet/rchip/pyu-rc_group_51_rohs_l.pdf
SW15 = SW_SPDT: Slide Switch SPDT Through Hole, Right Angle; Manufacturer: E-Switch; Datasheet: https://sten-eswitch-13110800-production.s3.amazonaws.com/system/asset/product_line/data_sheet/115/500.pdf
TP73-TP75 TP79-TP81 = TP1: Test Point 0.39"; Manufacturer: NA; Part Type: Test Point; Datasheet: NA
U31-U33 = TPS82130: Non-Isolated PoL Module DC DC Converter 1 Output 0.9 ~ 5V 3A 3V - 17V Input; Manufacturer: Texas Instruments; Part Type: Regulator; Datasheet: https://www.ti.com/general/docs/suppproductinfo.tsp?distId=10&gotoUrl=https%3A%2F%2Fwww.ti.com%2Flit%2Fgpn%2Ftps82130

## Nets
12V: C311.1 C317.1 D65.K F1.2 J17.A1 J17.A2 J17.A3 J17.A4 R538.2 U31.1(EN) U31.2(VIN) U33.1(EN) U33.2(VIN)
12V_FUSE: F1.1 SW15.3(NO)
12Vin: J1.1(+5V) SW15.2(COMMON)
GND: C300.2 C305.2 C307.2 C308.2 C309.2 C310.2 C311.2 C312.2 C313.2 C314.2 C315.2 C316.2 C317.2 C318.2 C319.2 D65.A1(Anode1) D65.A2(Anode2) D66.K(CATHODE) D68.K(CATHODE) J1.2(GND) J1.3(GND) J16.A5 J16.A6 J16.A19 J16.A22 J16.A25 J16.A29 J16.A32 J16.A35 J16.A38 J16.A53 J16.A64 J16.A67 J16.A70 J16.B11 J16.B19 J16.B22 J16.B25 J16.B29 J16.B32 J16.B35 J16.B38 J16.B64 J16.B67 J16.B70 J16.OA1 J16.OA4 J16.OA7 J16.OA10 J16.OA13 J16.OB1 J16.OB4 J16.OB7 J16.OB10 J16.OB13 J17.A5 J17.A6 J17.A19 J17.A22 J17.A25 J17.A29 J17.A32 J17.A35 J17.A38 J17.A53 J17.A64 J17.A67 J17.A70 J17.B11 J17.B19 J17.B22 J17.B25 J17.B29 J17.B32 J17.B35 J17.B38 J17.B64 J17.B67 J17.B70 J17.OA1 J17.OA4 J17.OA7 J17.OA10 J17.OA13 J17.OB1 J17.OB4 J17.OB7 J17.OB10 J17.OB13 J18.4 Q8.E Q9.E Q10.E Q11.E Q12.E Q13.E Q14.E Q15.E Q16.E Q17.E Q18.E Q19.E Q20.E Q21.E Q22.E Q23.E Q24.E Q25.E Q26.E Q27.E Q28.E Q29.E R510.2 R514.2 R518.2 R522.2 R530.2 R543.2 R544.2 R548.2 U29.4(GND) U30.4(GND) U31.3(GND) U31.9(EP) U32.3(GND) U32.9(EP) U33.3(GND) U33.9(EP) ; also on sheet 3 4 5 6 7 8 9 10 11 12 13 14 15 16 17 18 19 20 21 22 23 24
VCC_1V0: C314.1 R527.1 R528.1 R529.1 R535.1 R536.1 R540.2 R542.1 TP81.1 U32.4(VOUT) U32.5(VOUT) ; also on sheet 9 16
VCC_1V8: C309.1 C310.1 C318.1 J18.1 R516.1 R520.1 R525.1 R526.1 R533.1 R534.1 R547.1 R586.2 TP80.1 U29.8(VCC) U30.8(VCC) U33.4(VOUT) U33.5(VOUT) ; also on sheet 6 8 9 11 15 16 18 20
VCC_3V3: C312.1 C313.1 R457.2 R458.2 R459.2 R460.2 R461.2 R462.2 R463.2 R464.2 R465.2 R466.2 R467.2 R468.2 R469.2 R470.2 R471.2 R472.2 R473.2 R474.2 R475.2 R476.2 R477.2 R478.2 R479.2 R480.2 R481.2 R482.2 R483.2 R484.2 R485.2 R486.2 R487.2 R488.2 R489.2 R490.2 R491.2 R492.2 R493.2 R494.2 R495.2 R496.2 R497.2 R498.2 R499.2 R500.2 R501.2 R502.2 R503.2 R504.2 R505.2 R506.2 R508.1 R512.1 R537.2 R539.2 R541.1 R545.1 R546.1 R549.1 R585.2 TP79.1 U31.4(VOUT) U31.5(VOUT) U32.1(EN) U32.2(VIN) ; also on sheet 3 4 5 6 7 9 10 11 12 13 14 16 17 19 20 21 22 23 24
NX_BMC_LED_1: D25.K(CATHODE) ; also on sheet 13
NX_BMC_LED_2: D26.K(CATHODE) ; also on sheet 13
NX_BMC_LED_3: D27.K(CATHODE) ; also on sheet 13
NX_BMC_LED_4: D28.K(CATHODE) ; also on sheet 13
NX_BMC_LED_5: D29.K(CATHODE) ; also on sheet 13
NX_BMC_LED_6: D30.K(CATHODE) ; also on sheet 13
NX_BMC_LED_7: D31.K(CATHODE) ; also on sheet 13
NX_BMC_LED_8: D32.K(CATHODE) ; also on sheet 13
NX_BMC_LED_9: D33.K(CATHODE) ; also on sheet 13
NX_BMC_LED_10: D34.K(CATHODE) ; also on sheet 13
NX_PCH_LED_1: D37.K(CATHODE) ; also on sheet 14
NX_PCH_LED_2: D48.K(CATHODE) ; also on sheet 14
NX_PCH_LED_3: D39.K(CATHODE) ; also on sheet 14
NX_PCH_LED_4: D50.K(CATHODE) ; also on sheet 14
NX_PCH_LED_5: D42.K(CATHODE) ; also on sheet 14
NX_PCH_LED_6: D52.K(CATHODE) ; also on sheet 14
NX_PCH_LED_7: D43.K(CATHODE) ; also on sheet 14
NX_PCH_LED_8: D53.K(CATHODE) ; also on sheet 14
NX_PCH_LED_9: D44.K(CATHODE) ; also on sheet 14
NX_PCH_LED_10: D54.K(CATHODE) ; also on sheet 14
X3_LED_0: D55.K(CATHODE) ; also on sheet 19
X3_LED_1: D56.K(CATHODE) ; also on sheet 19
X3_LED_2: D57.K(CATHODE) ; also on sheet 19
X3_LED_3: D58.K(CATHODE) ; also on sheet 19
X3_LED_4: D59.K(CATHODE) ; also on sheet 19
X3_LED_5: D60.K(CATHODE) ; also on sheet 19
X3_LED_6: D61.K(CATHODE) ; also on sheet 19
X3_LED_7: D62.K(CATHODE) ; also on sheet 19
X3_LED_8: D63.K(CATHODE) ; also on sheet 19
X3_LED_9: D64.K(CATHODE) ; also on sheet 19
X03_SCM_TXCLK_N: C301.1 ; also on sheet 17
X03_SCM_TXCLK_N_GF: C301.2 J16.A23
X03_SCM_TXCLK_P: C299.1 ; also on sheet 17
X03_SCM_TXCLK_P_GF: C299.2 J16.A24
X03_SCM_TXD_N: C298.1 ; also on sheet 17
X03_SCM_TXD_N_GF: C298.2 J16.A20
X03_SCM_TXD_P: C297.1 ; also on sheet 17
X03_SCM_TXD_P_GF: C297.2 J16.A21
X05_HPM_RXCLK_N: J17.A23 R521.2 ; also on sheet 6
X05_HPM_RXCLK_P: J17.A24 R519.1 ; also on sheet 6
X05_HPM_RXD_N: J17.A20 R517.2 ; also on sheet 6
X05_HPM_RXD_P: J17.A21 R515.1 ; also on sheet 6
X05_HPM_TXCLK_N: J17.B23 ; also on sheet 6
X05_HPM_TXCLK_P: J17.B24 ; also on sheet 6
X05_HPM_TXD_N: J17.B20 ; also on sheet 6
X05_HPM_TXD_P: J17.B21 ; also on sheet 6
X5_I3C_SCL_KEEP_EN: U30.3(2C) ; also on sheet 8
X5_I3C_SCL_PU_EN: U30.7(1C) ; also on sheet 8
X5_I3C_SDA_KEEP_EN: U29.3(2C) ; also on sheet 8
X5_I3C_SDA_PU_EN: U29.7(1C) ; also on sheet 8
X5_I3C_VREF: R529.2 R530.1 ; also on sheet 8
X5_LED_0: Q8.B ; also on sheet 8
X5_LED_1: Q9.B ; also on sheet 8
X5_LED_2: Q10.B ; also on sheet 8
X5_LED_3: Q11.B ; also on sheet 8
X5_LED_4: Q12.B ; also on sheet 8
X5_LED_5: Q13.B ; also on sheet 8
X5_LED_6: Q14.B ; also on sheet 8
X5_LED_7: Q15.B ; also on sheet 8
X5_LED_8: Q16.B ; also on sheet 8
X5_LED_9: Q17.B ; also on sheet 8
X5_LED_10: Q18.B ; also on sheet 8
X5_LED_11: Q19.B ; also on sheet 8
X5_LED_12: Q20.B ; also on sheet 8
X5_LED_13: Q21.B ; also on sheet 8
X5_LED_14: Q22.B ; also on sheet 8
X5_LED_15: Q23.B ; also on sheet 8
X5_LED_16: Q24.B ; also on sheet 8
X5_LED_17: Q25.B ; also on sheet 8
X5_LED_18: Q26.B ; also on sheet 8
X5_LED_19: Q27.B ; also on sheet 8
X5_X3_I3C_SCL: J18.2 R531.2 R532.2 U30.1(1A) U30.5(2A) ; also on sheet 8 19
X5_X3_I3C_SDA: J18.3 R523.2 R524.2 U29.1(1A) U29.5(2A) ; also on sheet 8 19
X5_X3_SCL_HV_I_LV_PD: R532.1 ; also on sheet 8
X5_X3_SCL_LV_O: R531.1 ; also on sheet 8
X5_X3_SDA_HV_I_LV_PD: R524.1 ; also on sheet 8
X5_X3_SDA_LV_O: R523.1 ; also on sheet 8
XO3_SCM_RXCLK_N: C303.2 R513.2 ; also on sheet 19
XO3_SCM_RXCLK_N_GF: C303.1 J16.B23
XO3_SCM_RXCLK_P: C302.2 R511.1 ; also on sheet 19
XO3_SCM_RXCLK_P_GF: C302.1 J16.B24
XO3_SCM_RXD_N: C306.2 R509.2 ; also on sheet 19
XO3_SCM_RXD_N_GF: C306.1 J16.B20
XO3_SCM_RXD_P: C304.2 R507.1 ; also on sheet 19
XO3_SCM_RXD_P_GF: C304.1 J16.B21
N18564119: D15.A(ANODE) R457.1
N18564121: D16.A(ANODE) R458.1
N18564123: D17.A(ANODE) R459.1
N18564125: D18.A(ANODE) R460.1
N18564127: D19.A(ANODE) R461.1
N18564129: D20.A(ANODE) R462.1
N18564131: D21.A(ANODE) R463.1
N18564133: D22.A(ANODE) R464.1
N18564135: D23.A(ANODE) R465.1
N18564137: D24.A(ANODE) R466.1
N18564219: D15.K(CATHODE) Q8.C
N18564221: D16.K(CATHODE) Q9.C
N18564223: D17.K(CATHODE) Q10.C
N18564225: D18.K(CATHODE) Q11.C
N18564227: D19.K(CATHODE) Q12.C
N18564229: D20.K(CATHODE) Q13.C
N18564231: D21.K(CATHODE) Q14.C
N18564233: D22.K(CATHODE) Q15.C
N18564235: D23.K(CATHODE) Q16.C
N18564237: D24.K(CATHODE) Q17.C
N18566635: D45.A(ANODE) R487.1
N18566637: D35.A(ANODE) R488.1
N18566639: D46.A(ANODE) R489.1
N18566641: D36.A(ANODE) R490.1
N18566643: D47.A(ANODE) R491.1
N18566645: D38.A(ANODE) R492.1
N18566647: D49.A(ANODE) R493.1
N18566649: D40.A(ANODE) R494.1
N18566651: D51.A(ANODE) R495.1
N18566653: D41.A(ANODE) R496.1
N18566735: D45.K(CATHODE) Q18.C
N18566737: D35.K(CATHODE) Q19.C
N18566739: D46.K(CATHODE) Q20.C
N18566741: D36.K(CATHODE) Q21.C
N18566743: D47.K(CATHODE) Q22.C
N18566745: D38.K(CATHODE) Q23.C
N18566747: D49.K(CATHODE) Q24.C
N18566749: D40.K(CATHODE) Q25.C
N18566751: D51.K(CATHODE) Q26.C
N18566753: D41.K(CATHODE) Q27.C
N18602789: D25.A(ANODE) R467.1
N18602791: D26.A(ANODE) R468.1
N18602793: D27.A(ANODE) R469.1
N18602795: D28.A(ANODE) R470.1
N18602797: D29.A(ANODE) R471.1
N18602799: D30.A(ANODE) R472.1
N18602801: D31.A(ANODE) R473.1
N18602803: D32.A(ANODE) R474.1
N18602805: D33.A(ANODE) R475.1
N18602807: D34.A(ANODE) R476.1
N18613493: D37.A(ANODE) R477.1
N18613495: D48.A(ANODE) R478.1
N18613497: D39.A(ANODE) R479.1
N18613499: D50.A(ANODE) R480.1
N18613501: D42.A(ANODE) R481.1
N18613503: D52.A(ANODE) R482.1
N18613505: D43.A(ANODE) R483.1
N18613507: D53.A(ANODE) R484.1
N18613509: D44.A(ANODE) R485.1
N18613511: D54.A(ANODE) R486.1
N18705240: R525.2 R527.2 U29.2(1B)
N18705319: R526.2 R528.2 U29.6(2B)
N18705494: R533.2 R535.2 U30.2(1B)
N18705496: R534.2 R536.2 U30.6(2B)
N19346711: C300.1 R507.2 R508.2 R509.1 R510.1
N19347611: C305.1 R511.2 R512.2 R513.1 R514.1
N19350146: C307.1 R515.2 R516.2 R517.1 R518.1
N19350224: C308.1 R519.2 R520.2 R521.1 R522.1
N19365925: D67.K(CATHODE) Q28.C
N19367414: Q28.B R540.1
N19368163: D67.A(ANODE) R537.1
N19369016: D68.A(ANODE) R539.1
N19380211: R541.2 R543.1 U31.6(FB)
N19380531: C315.1 U31.8(SS/TR)
N19380754: R545.2 TP73.1 U31.7(PG)
N19385070: R542.2 R544.1 U32.6(FB)
N19385072: C316.1 U32.8(SS/TR)
N19385096: R546.2 TP74.1 U32.7(PG)
N19409561: R547.2 R548.1 U33.6(FB)
N19409563: C319.1 U33.8(SS/TR)
N19409587: R549.2 TP75.1 U33.7(PG)
N19601698: D55.A(ANODE) R497.1
N19601700: D56.A(ANODE) R498.1
N19601702: D57.A(ANODE) R499.1
N19601704: D58.A(ANODE) R500.1
N19601706: D59.A(ANODE) R501.1
N19601708: D60.A(ANODE) R502.1
N19601710: D61.A(ANODE) R503.1
N19601712: D62.A(ANODE) R504.1
N19601714: D63.A(ANODE) R505.1
N19601716: D64.A(ANODE) R506.1
N20195165: D69.A(ANODE) R585.1
N20195175: D69.K(CATHODE) Q29.C
N20195200: Q29.B R586.1
N20636106: D66.A(ANODE) R538.1

Not connected (* = marked no-connect by the designer): J16 A1 A2 A3 A4 A7 A8 A9 A10 A11 A12 A13 A14 A15 A16 A17 A18 A26 A27 A28 A30 A31 A33 A34 A36 A37 A39 A40 A41 A42 A43 A44 A45 A46 A47 A48 A49 A50 A51 A52 A54 A55 A56 A57 A58 A59 A60 A61 A62 A63 A65 A66 A68 A69 B1 B2 B3 B4 B5 B6 B7 B8 B9 B10 B12 B13 B14 B15 B16 B17 B18 B26 B27 B28 B30 B31 B33 B34 B36 B37 B39 B40 B41 B42 B43 B44 B45 B46 B47 B48 B49 B50 B51 B52 B53 B54 B55 B56 B57 B58 B59 B60 B61 B62 B63 B65 B66 B68 B69 OA2 OA3 OA5 OA6 OA8 OA9 OA11 OA12 OA14 OB2 OB3 OB5 OB6 OB8 OB9 OB11 OB12 OB14; J17 A7 A8 A9 A10 A11 A12 A13 A14 A15 A16 A17 A18 A26 A27 A28 A30 A31 A33 A34 A36 A37 A39 A40 A41 A42 A43 A44 A45 A46 A47 A48 A49 A50 A51 A52 A54 A55 A56 A57 A58 A59 A60 A61 A62 A63 A65 A66 A68 A69 B1 B2 B3 B4 B5 B6 B7 B8 B9 B10 B12 B13 B14 B15 B16 B17 B18 B26 B27 B28 B30 B31 B33 B34 B36 B37 B39 B40 B41 B42 B43 B44 B45 B46 B47 B48 B49 B50 B51 B52 B53 B54 B55 B56 B57 B58 B59 B60 B61 B62 B63 B65 B66 B68 B69 OA2 OA3 OA5 OA6 OA8 OA9 OA11 OA12 OA14 OB2 OB3 OB5 OB6 OB8 OB9 OB11 OB12 OB14; MH1 1*; MH2 1*; MH3 1*; MH4 1*; SW15 1(NC)*

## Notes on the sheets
sheet 25
- XO5D LEDs
- CPNX BMC LEDs
- LEDs Signal Map
- U2
  Pin
- Signal
- LED
- LEDs Signal Map
- L24
- NX_BMC_LED_1
- D25
- U1
  Pin
- Signal
- LED
- L23
- NX_BMC_LED_2
- D26
- L22
- NX_BMC_LED_3
- D27
- R14
- X5_LED_0
- D15
- L20
- NX_BMC_LED_4
- D28
- R15
- X5_LED_1
- D16
- L19
- NX_BMC_LED_5
- D29
- N16
- X5_LED_2
- D17
- M26
- NX_BMC_LED_6
- D30
- P16
- X5_LED_3
- D18
- M17
- X5_LED_4
- D19
- N26
- NX_BMC_LED_7
- D31
- N25
- NX_BMC_LED_8
- D32
- M16
- X5_LED_5
- D20
- N24
- NX_BMC_LED_9
- D33
- P19
- X5_LED_6
- D21
- P20
- X5_LED_7
- D22
- N22
- NX_BMC_LED_10
- D34
- P17
- X5_LED_8
- D23
- CPNX PCH LEDs
- P18
- X5_LED_9
- D24
- LEDs Signal Map
- W10
- X5_LED_10
- D45
- U21
  pin
- P12
- X5_LED_11
- D35
- Signal
- LED
- R12
- X5_LED_12
- D46
- V4
- NX_PCH_LED_1
- D37
- P11
- X5_LED_13
- D36
- V5
- NX_PCH_LED_2
- D48
- V12
- X5_LED_14
- D47
- V6
- NX_PCH_LED_3
- D39
- W11
- X5_LED_15
- D38
- W7
- NX_PCH_LED_4
- D50
- V11
- X5_LED_16
- D49
- U12
- X5_LED_17
- D40
- W6
- NX_PCH_LED_5
- D42
- W5
- NX_PCH_LED_6
- D52
- W13
- X5_LED_18
- D51
- W2
- NX_PCH_LED_7
- D43
- W12
- X5_LED_19
- D41
- W1
- NX_PCH_LED_8
- D53
- Y1
- NX_PCH_LED_9
- D44
- Y4
- NX_PCH_LED_10
- D54
- XO3D LEDs
- LEDs Signal Map
- U3
  Pin
- Signal
- LED
- T1
- X3_LED_0
- D55
- U1
- X3_LED_1
- D56
- R2
- X3_LED_2
- D57
- T2
- X3_LED_3
- D58
- R3
- X3_LED_4
- D59
- T3
- X3_LED_5
- D60
- R4
- X3_LED_6
- D61
- T4
- X3_LED_7
- D62
- R5
- X3_LED_8
- D63
- T5
- X3_LED_9
- D64
sheet 26
- XO3D SCM
- DC-SCM
- XO5D HPM
sheet 27
- DNP
- DNP
sheet 28
- Power On LED Indications
- +12V
- POWER INPUT
- Right angle
  mount, cable
  to board edge
- 12V
- 1.0V
- 1.8V
- 3.3V
- 3A
- 3A
- Vout = 0.8*(1 + Rtop/Rbot)
  0.8(1 + 127K/40.2K) = 3.33V
- Vout = 0.8*(1 + Rtop/Rbot)
  0.8(1 + 10K/40.2K) = 1.0V
- 3A
- Vout = 0.8*(1 + Rtop/Rbot)
  0.8(1 + 51K/40.2K) = 1.81V
